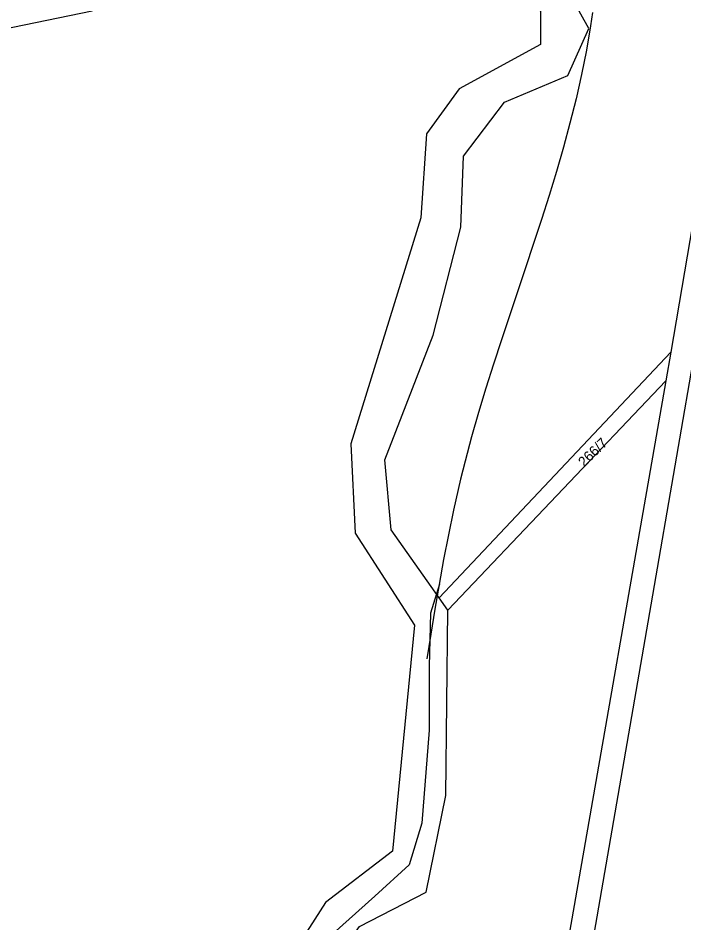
# Model space of a CAD drawing. Extents: x -555757 to -553364, y -1100723 to -1096439.
# Drawn here: x -553791.4 to -553659, y -1098755.2 to -1098575.2 of the extents above; entities that cross this region are included whole.
import ezdxf

# ---------------------------------------------------------------- set-up
doc = ezdxf.new("R2010")
doc.units = 0
for name, color, linetype in [('01_HLADINA', 7, 'Continuous'), ('C$SLO$PARCELY', 7, 'Continuous'), ('HRANICE$PARCELY', 7, 'Continuous'), ('HRANICE_PARCEL', 7, 'Continuous')]:
    doc.layers.add(name, color=color, linetype=linetype)

msp = doc.modelspace()

# ---------------------------------------------------------------- linework, layer by layer
at = {"layer": '01_HLADINA'}
for p, q in [((-553707.62, -1098687.83), (-553709.4, -1098693.62)), ((-553709.4, -1098693.62), (-553709.66, -1098704.18)), ((-553709.66, -1098704.18), (-553709.66, -1098716.89)), ((-553709.66, -1098716.89), (-553711.15, -1098735.41)), ((-553711.15, -1098735.41), (-553713.62, -1098743.71)), ((-553713.62, -1098743.71), (-553720.47, -1098749.91)), ((-553720.47, -1098749.91), (-553730.67, -1098759.06))]:
    msp.add_line(p, q, dxfattribs=at)
msp.add_lwpolyline([(-553677.2, -1098574.15), (-553677.58, -1098576.77), (-553678.41, -1098581.64), (-553679.38, -1098586.49), (-553680.48, -1098591.32), (-553681.69, -1098596.14), (-553682.99, -1098600.95), (-553684.38, -1098605.75), (-553685.84, -1098610.55), (-553687.36, -1098615.34), (-553688.92, -1098620.12), (-553690.51, -1098624.91), (-553692.11, -1098629.69), (-553693.71, -1098634.48), (-553695.3, -1098639.28), (-553696.86, -1098644.08), (-553698.38, -1098648.89), (-553699.84, -1098653.71), (-553701.23, -1098658.55), (-553702.54, -1098663.4), (-553703.43, -1098666.98), (-553704.85, -1098673.16), (-553705.86, -1098678.06), (-553706.8, -1098682.98), (-553707.68, -1098687.91), (-553708.52, -1098692.84), (-553709.32, -1098697.79), (-553710.11, -1098702.73)], dxfattribs=at)
at = {"layer": 'HRANICE$PARCELY'}
for p, q in [((-553661.65, -1098641.68), (-553707.66, -1098690.59)), ((-553661.65, -1098641.68), (-553662.65, -1098647.4)), ((-553705.94, -1098693.02), (-553662.65, -1098647.4)), ((-553705.94, -1098693.02), (-553707.66, -1098690.59))]:
    msp.add_line(p, q, dxfattribs=at)
for points in [[(-553595.18, -1098243.75), (-553613.13, -1098354.33), (-553623.73, -1098418.67), (-553661.65, -1098641.68)], [(-553707.66, -1098690.59), (-553717.24, -1098677.04), (-553718.46, -1098663.12), (-553716.28, -1098657.5), (-553708.86, -1098638.32), (-553703.35, -1098616.82), (-553702.87, -1098602.73), (-553694.71, -1098592), (-553682.1, -1098586.67), (-553677.92, -1098577.33), (-553683.32, -1098567.65), (-553696.06, -1098553.44), (-553705.87, -1098548.72), (-553715.63, -1098521.12), (-553734.37, -1098522.56), (-553745.6, -1098531.3), (-553752.26, -1098530.69)], [(-553757.98, -1098538.78), (-553741.87, -1098538.11), (-553731.71, -1098530.07), (-553720.57, -1098528.29), (-553712.12, -1098552.02), (-553687.56, -1098573.84), (-553687.57, -1098580.52), (-553703.69, -1098589.3), (-553710.2, -1098598.28), (-553711.31, -1098614.96), (-553725.23, -1098659.96), (-553724.39, -1098677.73), (-553712.57, -1098696.02), (-553716.96, -1098740.99), (-553730.31, -1098751.21), (-553736.18, -1098760.42)], [(-553656.41, -1098638.56), (-553665.29, -1098690.06), (-553676.92, -1098757.5)], [(-553662.65, -1098647.4), (-553681.77, -1098757.12), (-553690.36, -1098843.27), (-553696.99, -1098909.8), (-553702.51, -1098963.05), (-553706.94, -1098997.02), (-553700.79, -1099020.07), (-553692.59, -1099050.83), (-553646.48, -1099083.36)], [(-553803.25, -1098963.95), (-553785, -1098965.14), (-553765.34, -1098958.27), (-553757.12, -1098951.78), (-553740.46, -1098950.96), (-553732.16, -1098943.13), (-553731.1, -1098931.57), (-553735.31, -1098917.77), (-553709.31, -1098860.02), (-553710.45, -1098843.35), (-553710.93, -1098836.42), (-553710.2, -1098811.11), (-553705.91, -1098793.48), (-553708.33, -1098792.19), (-553710.86, -1098790.84), (-553726.88, -1098782.31), (-553732.18, -1098775.53), (-553729.4, -1098764.38), (-553723.54, -1098755.94), (-553710.26, -1098749.14), (-553706.33, -1098729.9), (-553705.94, -1098693.02)]]:
    msp.add_lwpolyline(points, dxfattribs=at)
at = {"layer": 'HRANICE_PARCEL'}
msp.add_lwpolyline([(-553757.98, -1098538.78), (-553776.66, -1098573.9), (-553819.55, -1098582.71)], dxfattribs=at)

# ---------------------------------------------------------------- texts
at = {"layer": 'C$SLO$PARCELY'}
msp.add_text('266/7', height=2, rotation=44, dxfattribs=at).set_placement((-553678.88, -1098664.66))

doc.saveas('drawing.dxf')
